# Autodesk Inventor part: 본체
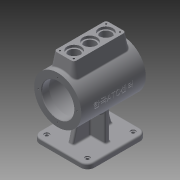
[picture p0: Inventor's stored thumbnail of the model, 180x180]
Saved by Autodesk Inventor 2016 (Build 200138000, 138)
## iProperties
Created: 2015-11
Part Number: 본체
Material: 일반
Document SubType Name: Modeling
Designer: mduedu
Density: 1 g/cm^3
Appearance: 기본값
Author: mduedu
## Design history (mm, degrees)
sketch "스케치2"
  geometry: C1 r 47.5 at (0, 0); 1 further point
  constraints: 1 centre point, 1 coincident
  dimensions: "d147" = 95 diameter of C1
extrude "돌출1" new body sketch "스케치2" stored distance "d12" = 130; taper "d13" = 0 deg
feature "쉘1" dims "d31" = 15, "d32" = 6, "d33" = 15
sketch "스케치5"
  geometry: C1 r 32.5 at (0, 0); 1 further point
  constraints: 1 centre point, 1 coincident
  dimensions: "d34" = 65 diameter of C1
extrude "돌출3" cut sketch "스케치5" stored distance "d36" = 3; taper "d37" = 0 deg
node "작업 평면1"
sketch "스케치6"
  geometry: L1 (-60, -55)-(60, -55); L2 (60, -55)-(60, 55); L3 (60, 55)-(-60, 55); L4 (-60, 55)-(-60, -55); L5 (-60, -55)-(60, 55); L6 (60, -55)-(-60, 55); 1 further point
  constraints: 12 end point, 2 midpoint, 2 parallel, 1 horizontal, 1 perpendicular
  dimensions: "d41" = 110 distance of L3.end L1.start; "d43" = 120 distance of L2.end L3.end
extrude "돌출4" join sketch "스케치6" distance "d44" = 10; taper "d45" = 0 deg
sketch "스케치19"
  geometry: L1 (-5, 35)-(5, 35); L2 (5, 35)-(5, -35); L3 (5, -35)-(-5, -35); L4 (-5, -35)-(-5, 35); L5 (-60, 55)-(-60, -55) reference; L6 (5, -35)-(-5, 35); L7 (5, 35)-(-5, -35); 3 further points
  constraints: 12 end point, 2 midpoint, 2 parallel, 1 coincident, 1 horizontal, 1 horizontal alignment, 1 perpendicular
  dimensions: "d151" = 10 distance of L1.start L1.end; "d152" = 70 distance of L3.end L1.start
extrude "돌출9" join sketch "스케치19" stored distance "d153" = 10; taper "d154" = 0 deg
sketch "스케치20"
  geometry: L1 (65, 32.5)-(50, 32.5) reference; L2 (50, 32.5)-(50, 41.5) reference; L3 (50, 41.5)-(-50, 41.5) reference; L4 (-50, 41.5)-(-50, 32.5) reference; L5 (-50, 32.5)-(-65, 32.5) reference; L6 (-65, 32.5)-(-65, 47.5) reference; L7 (-65, 47.5)-(65, 47.5) reference; L8 (65, 47.5)-(65, 32.5) reference; L9 (50, -32.5)-(65, -32.5) reference; L10 (65, -32.5)-(65, -47.5) reference; L11 (65, -47.5)-(5, -47.5) reference; L12 (5, -47.5)-(5, -90) reference; L13 (5, -90)-(60, -90) reference; L14 (60, -90)-(60, -100) reference; L15 (60, -100)-(-60, -100) reference; L16 (-60, -100)-(-60, -90) reference; L17 (-60, -90)-(-5, -90) reference; L18 (-5, -90)-(-5, -47.5) reference; L19 (-5, -47.5)-(-65, -47.5) reference; L20 (-65, -47.5)-(-65, -32.5) reference; L21 (-65, -32.5)-(-50, -32.5) reference; L22 (-50, -32.5)-(-50, -41.5) reference; L23 (-50, -41.5)-(50, -41.5) reference; L24 (50, -41.5)-(50, -32.5) reference; L25 (-40, -90)-(-28.612, -47.5); 1 further point
  constraints: 2 end point, 2 point on line
  dimensions: "d155" = 20 distance from line of L25.start L16; "d156" = 105 deg angle of L25 L17
feature "리브2" sketch "스케치20" dims "d157" = 1, "d158" = 10, "d159" = 0, "d160" = 0, "d161" = 1, "d162" = 1
fillet "모깎기21" dims "d163" = 3
fillet "모깎기22" dims "d164" = 3
fillet "모깎기23" dims "d165" = 3
sketch "스케치21" dims "d166" = 78
  geometry: 3 further points
  constraints: 2 horizontal alignment, 1 coincident, 2 other
hole "구멍6" sketch "스케치21" at (39, 0) diameter "d168" = 3.242; stored, may be unused: countersink angle "d172" = 90 deg, drill point angle "d174" = 118 deg; dims "d169" = 9, "d170" = 4, "d171" = 2, "d173" = 11
node "작업 평면2"
sketch "스케치13"
  geometry: L1 (-52.5, -20)-(52.5, -20); L2 (52.5, -20)-(52.5, 20); L3 (52.5, 20)-(-52.5, 20); L4 (-52.5, 20)-(-52.5, -20); L5 (-52.5, -20)-(52.5, 20); L6 (52.5, -20)-(-52.5, 20); 1 further point
  constraints: 12 end point, 2 midpoint, 2 parallel, 1 horizontal, 1 perpendicular
  dimensions: "d93" = 105 distance of L2.end L3.end; "d95" = 40 distance of L1.end L2.end
extrude "돌출8" join sketch "스케치13" stored distance "d96" = 80; taper "d97" = 0 deg
fillet "모깎기15" dims "d98" = 5
feature "면 기울기1" dims angle "d178" = 10 deg
fillet "모깎기24" dims "d179" = 3
sketch "스케치14"
  geometry: L1 (-52.5, 15)-(-52.5, -15) reference; L2 (52.5, -15)-(52.5, 15) reference; L3 (-52.5, 0)-(52.5, 0); 4 further points
  constraints: 2 end point, 2 midpoint, 2 point on line, 1 coincident
  dimensions: "d100" = 32 distance of point (-32, 0) point (0, 0); "d102" = 32 distance of point (32, 0) point (0, 0) (derived)
hole "구멍3" sketch "스케치14" at (-32, 0), (0, 0), (32, 0) diameter "d103" = 22; stored, may be unused: countersink angle "d107" = 90 deg, drill point angle "d109" = 118 deg; dims "d104" = 8, "d105" = 28, "d106" = 5, "d108" = 10
sketch "스케치15"
  geometry: L1 (46.5, -14)-(-46.5, -14); L2 (-46.5, -14)-(-46.5, 14); L3 (-46.5, 14)-(46.5, 14); L4 (46.5, 14)-(46.5, -14); L5 (46.5, -14)-(-46.5, 14); L6 (-46.5, -14)-(46.5, 14); L7 (47.5, 20)-(-47.5, 20) reference; L8 (-52.5, 15)-(-52.5, -15) reference; 5 further points
  constraints: 12 end point, 4 coincident, 2 midpoint, 2 parallel, 1 horizontal, 1 perpendicular
  dimensions: "d110" = 6 distance between parallel lines of L3 L7; "d111" = 6 distance between parallel lines of L2 L8
hole "구멍4" sketch "스케치15" at (-46.5, 14), (46.5, 14), (46.5, -14), (-46.5, -14) diameter "d112" = 3.242; stored, may be unused: countersink angle "d116" = 90 deg, drill point angle "d118" = 118 deg; dims "d113" = 10, "d114" = 28, "d115" = 5, "d117" = 13
node "작업 평면3"
sketch "스케치22"
  geometry: 2 further points
  constraints: 1 coincident, 1 other
feature "엠보싱3" sketch "스케치22" dims "d31" = 15, "d181" = 0.5, "d182" = 0
chamfer "모따기2" distance "d183" = 1; stored, may be unused: second distance "d184" = 2, angle "d185" = 45 deg
fillet "모깎기25" dims "d186" = 14
sketch "스케치23"
  geometry: L1 (46, 55)-(-46, 55) reference; L2 (60, -41)-(60, 41) reference; L3 (-46, -55)-(46, -55) reference; L4 (-60, 41)-(-60, -41) reference; A1 r 14 centre (-46, 41) between (-46, 55) and (-60, 41) reference; A2 r 14 centre (46, 41) between (60, 41) and (46, 55) reference; A3 r 14 centre (46, -41) between (46, -55) and (60, -41) reference; A4 r 14 centre (-46, -41) between (-60, -41) and (-46, -55) reference; 1 further point
hole "구멍7" sketch "스케치23" at (-46, 41), (-46, -41), (46, -41), (46, 41) diameter "d187" = 6; stored, may be unused: countersink angle "d191" = 90 deg, drill point angle "d193" = 118 deg; dims "d188" = 9, "d189" = 10, "d190" = 2, "d192" = 11
fillet "모깎기26" dims "d194" = 3
node "솔리드1"
mirror "대칭6"
pattern_circular "원형 패턴2" dims angle "d176" = 360 deg
mirror "대칭5"
node "투영된 루프2"
node "절단 모서리 투영1"
